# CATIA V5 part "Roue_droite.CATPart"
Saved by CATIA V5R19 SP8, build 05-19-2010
Part number: Roue_droite
Bounding box of the stored display mesh (mm): x 825 to 1125, y 1050 to 1950, z -1299.802 to -400.198
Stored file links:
  G:\EU_thinkMotion\CFAO_2010\MMS_groupe2\MMS_groupe2\OK\mmartini\mmartiniCFAO\Roue_droite.CATPart
  C:\Users\Mathieu Martini\Desktop\CFAO\Animation\CFAO.CATProduct
  G:\EU_thinkMotion\CFAO_2010\MMS_groupe2\MMS_groupe2\OK\mmartini\mmartiniCFAO\Squelette.CATPart
  G:\EU_thinkMotion\CFAO_2010\MMS_groupe2\MMS_groupe2\OK\mmartini\mmartiniCFAO\Roue_gauche.CATPart
  G:\EU_thinkMotion\CFAO_2010\MMS_groupe2\MMS_groupe2\OK\mmartini\mmartiniCFAO\Jambe_droite.CATPart
  G:\EU_thinkMotion\CFAO_2010\MMS_groupe2\MMS_groupe2\OK\mmartini\mmartiniCFAO\Jambe_gauche.CATPart
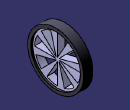
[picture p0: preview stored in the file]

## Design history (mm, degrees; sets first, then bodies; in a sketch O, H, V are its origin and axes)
External parameters (linked from other documents)
  External.diametre_canon = 150 mm
  External.diametre_verin = 120 mm
AxisSystem1: origin (0, 0, 0), X (1, 0, 0), Y (0, 1, 0), Z (0, 0, 1)
Set1
  Sketch1 on Plane1, origin (975, 0, 0), H (0, 1, 0), V (0, 0, 1)
    circle A1 centre (1500, -850) radius 450
    point P1 (1500, -850)
    reference projected point E1 (1500, -850) from Line1
    reference intersected line E2 through (0, -1300) direction (-1, 0) from Plane2
    circle A2 centre (1500, -850) radius 400
    distance A2 A1 = 50 {= External.diametre_canon /3}
    coincidence: P1 E1
    tangency: A1 E2
Set2
  Plane1: linked copy from another document
  Line1 "axe_roue": linked copy from another document
  Plane2 "sol": linked copy from another document
  Point1: linked copy from another document
  Plane3: linked copy from another document
  DatumCurve1: linked copy from another document
  Point2: linked copy from another document
  DatumCurve2: linked copy from another document
  DatumCurve3: linked copy from another document
  Point3: linked copy from another document
  DatumSurface1: linked copy from another document
  Point4: linked copy from another document
Body1 (main body)
  Pad1: profile Sketch1, direction (1, 0, 0), length 150 {= External.diametre_canon}
  Sketch2 on Plane1, origin (975, 0, 0), H (0, 1, 0), V (0, 0, 1)
    projected circle E1 centre (1500, -850) radius 400 from edge [face of Pad1 from Sketch1.A2 | start face of Pad1]
  Pad2: profile Sketch2, direction (1, 0, 0), length 120 {= External.diametre_canon -External.diametre_canon /5}
  Sketch3 on Plane1, origin (975, 0, 0), H (0, 1, 0), V (0, 0, 1)
    axis line L1 (1500, -342.7295) -> (1500, -850)
    point P2 (1500, -850)
    reference projected point E1 (1500, -850) from Point1
    line L2 (1500, -820) -> (1500, -480)
    point P3 (1500, -820)
    point P4 (1500, -480)
    reference projected circle E2 centre (1500, -850) radius 400 from edge [face of Pad1 from Sketch1.A2 | end face of Pad2]
    arc A1 centre (1500, -820) radius 340 from (1670, -525.5514) to (1500, -480) ccw
    line L3 (1500, -820) -> (1670, -525.5514)
    point P6 (1500, -480)
    distance E2 P4 = 30 {= External.diametre_canon /5}
    distance P3 P2 = 30 {= External.diametre_canon /5}
    angle L2 L3 = 30
    vertical: L1 V, L2 V
    coincidence: P2 E1, P3 L1, A1 P4, L1 P6, P4 P6
  Pocket1: profile Sketch3, direction (1, 0, 0), through (limit type 6)
  CircPattern1: of Pocket1, instances 8, angular step 45, axis from Line1
  Sketch4 on Plane1, origin (975, 0, 0), H (0, 1, 0), V (0, 0, 1)
    circle A1 centre (1500, -850) radius 30
    point P1 (1500, -850)
    reference projected point E1 (1500, -850) from Line1
    radius A1 = 30 {= External.diametre_canon /5}
    coincidence: P1 E1
  Pad3: profile Sketch4, direction (-1, 0, 0), length 150 {= External.diametre_canon}, opposite side length 1.5 {= External.diametre_canon /100}
  Sketch5 on face of Pad2, origin (975, 0, 0), H (0, -1, 0), V (0, 0, 1)
    point P1 (-1376.856, -501.0938)
    circle A1 centre (-1500, -850) radius 370
    point P2 (-1500, -850)
    point P3 (-1376.856, -501.0938)
    reference projected point E1 (-1500, -850) from Line1
    projected point E2 (-1238.3705, -588.3705) from vertex [face of Pad2 | face of CircPattern1 | face of CircPattern1]
    coincidence: P2 E1, A1 E2, P1 P3
  Pocket2: profile Sketch5, direction (1, 0, 0), length 1.5 {= External.diametre_canon /100}
  Line2: type PtDir, RefPoint Point2, Direction DatumCurve2, Start 0, End 20
  Line3: type PtDir, RefPoint Point3, Direction DatumCurve3, Start 0, End 20
  Sketch6 on face of DatumSurface1, origin (795, 0, 0), H (0, 1, 0), V (0, 0, 1)
    circle A1 centre (-900, 150) radius 1582.1267
    point P1 (-900, 150)
    reference projected point E1 (-900, 150) from Point4
    reference projected point E2 (-2475, 0) from Point2
    coincidence: P1 E1, A1 E2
